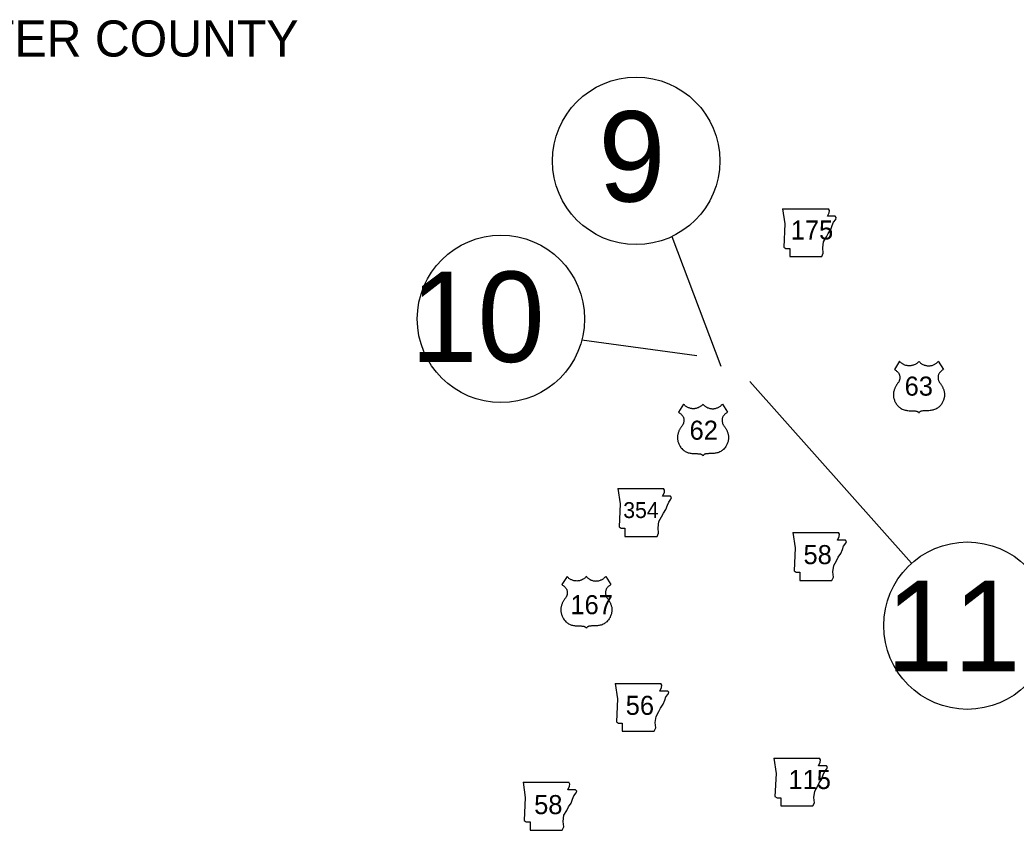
# Model space of a CAD drawing. Extents: x -819161 to 80911, y -6604 to 768454.
# Drawn here: x 45921 to 48407, y 4696 to 6716 of the extents above; entities that cross this region are included whole.
import ezdxf

# ---------------------------------------------------------------- set-up
doc = ezdxf.new("R2010")
doc.units = 0
for name, color, linetype in [('Default', 7, 'Continuous'), ('Level 21', 7, 'Continuous'), ('Level 22', 7, 'Continuous')]:
    doc.layers.add(name, color=color, linetype=linetype)

msp = doc.modelspace()

# ---------------------------------------------------------------- linework, layer by layer
at = {"layer": 'Default'}
for points in [[(47548.1, 6175.7), (47670.5, 5852.4)], [(47323.6, 5917.9), (47610.3, 5879.4)], [(47742.7, 5814.3), (48146.4, 5361.1)]]:
    msp.add_lwpolyline(points, dxfattribs=at)
for centre in [(47458.9, 6364.4), (47121.5, 5970.4), (48285.3, 5205.4)]:
    msp.add_circle(centre, 208.7, dxfattribs=at)
at = {"layer": 'Level 21'}
for p, q in [((47824.5, 6245.2), (47830.2, 6207.2)), ((47941.2, 6240.8), (47938.6, 6245.2)), ((47940.6, 6235.1), (47941.2, 6240.8)), ((47936.2, 6226.2), (47940.6, 6235.1)), ((47955.8, 6226.2), (47936.2, 6226.2)), ((47951.4, 6211.6), (47957.1, 6218.6)), ((47958.4, 6223), (47955.8, 6226.2)), ((47957.1, 6218.6), (47958.4, 6223)), ((47830.2, 6207.2), (47827.7, 6149.4)), ((47938.1, 6183.7), (47944.4, 6193.2)), ((47944.4, 6193.2), (47948.2, 6203.4)), ((47948.2, 6203.4), (47951.4, 6211.6)), ((47926.6, 6162.7), (47933.6, 6174.8)), ((47933.6, 6174.8), (47938.1, 6183.7)), ((47827.7, 6149.4), (47832.8, 6146.3)), ((47832.8, 6146.3), (47842.3, 6146.3)), ((47842.3, 6146.3), (47842.3, 6126)), ((47924.7, 6147.5), (47926.6, 6162.7)), ((47926, 6134.2), (47924.7, 6147.5)), ((47842.3, 6126), (47922.2, 6126)), ((47922.2, 6126), (47926, 6134.2)), ((47413.3, 5547.4), (47419, 5509.3)), ((47530.1, 5542.9), (47527.4, 5547.3)), ((47525, 5528.3), (47529.4, 5537.2)), ((47544.7, 5528.3), (47525, 5528.3)), ((47529.4, 5537.2), (47530.1, 5542.9)), ((47540.2, 5513.7), (47545.9, 5520.7)), ((47547.2, 5525.2), (47544.7, 5528.3)), ((47545.9, 5520.7), (47547.2, 5525.2)), ((47419, 5509.3), (47416.5, 5451.6)), ((47526.9, 5485.8), (47533.2, 5495.3)), ((47533.2, 5495.3), (47537.1, 5505.5)), ((47537.1, 5505.5), (47540.2, 5513.7)), ((47515.5, 5464.9), (47522.5, 5476.9)), ((47522.5, 5476.9), (47526.9, 5485.8)), ((47416.5, 5451.6), (47421.6, 5448.4)), ((47421.6, 5448.4), (47431.1, 5448.4)), ((47431.1, 5448.4), (47431.1, 5428.1)), ((47513.6, 5449.7), (47515.5, 5464.9)), ((47514.8, 5436.3), (47513.6, 5449.7)), ((47431.1, 5428.1), (47511, 5428.1)), ((47511, 5428.1), (47514.8, 5436.3)), ((47849.8, 5437.6), (47855.6, 5399.5)), ((47961.5, 5418.6), (47965.9, 5427.5)), ((47966.6, 5433.2), (47963.9, 5437.6)), ((47965.9, 5427.5), (47966.6, 5433.2)), ((47855.6, 5399.5), (47853, 5341.8)), ((47981.2, 5418.6), (47961.5, 5418.6)), ((47969.8, 5385.6), (47973.6, 5395.7)), ((47973.6, 5395.7), (47976.7, 5404)), ((47976.7, 5404), (47982.4, 5411)), ((47983.7, 5415.4), (47981.2, 5418.6)), ((47982.4, 5411), (47983.7, 5415.4)), ((47959, 5367.2), (47963.4, 5376.1)), ((47963.4, 5376.1), (47969.8, 5385.6)), ((47950.1, 5339.9), (47952, 5355.1)), ((47952, 5355.1), (47959, 5367.2)), ((47853, 5341.8), (47858.1, 5338.6)), ((47858.1, 5338.6), (47867.6, 5338.6)), ((47867.6, 5338.6), (47867.6, 5318.3)), ((47947.5, 5318.3), (47951.4, 5326.6)), ((47951.4, 5326.6), (47950.1, 5339.9)), ((47867.6, 5318.3), (47947.5, 5318.3)), ((47406.5, 5061.4), (47412.2, 5023.3)), ((47518.1, 5042.4), (47522.6, 5051.3)), ((47523.2, 5057), (47520.6, 5061.4)), ((47522.6, 5051.3), (47523.2, 5057)), ((47412.2, 5023.3), (47409.6, 4965.6)), ((47537.8, 5042.4), (47518.1, 5042.4)), ((47530.2, 5019.5), (47533.4, 5027.8)), ((47533.4, 5027.8), (47539.1, 5034.8)), ((47540.3, 5039.2), (47537.8, 5042.4)), ((47539.1, 5034.8), (47540.3, 5039.2)), ((47515.6, 4991), (47520, 4999.9)), ((47520, 4999.9), (47526.4, 5009.4)), ((47526.4, 5009.4), (47530.2, 5019.5)), ((47506.7, 4963.7), (47508.6, 4978.9)), ((47508.6, 4978.9), (47515.6, 4991)), ((47409.6, 4965.6), (47414.7, 4962.4)), ((47414.7, 4962.4), (47424.2, 4962.4)), ((47424.2, 4962.4), (47424.2, 4942.1)), ((47504.2, 4942.1), (47508, 4950.4)), ((47508, 4950.4), (47506.7, 4963.7)), ((47424.2, 4942.1), (47504.2, 4942.1)), ((47802.3, 4874.9), (47808, 4836.9)), ((47919, 4870.5), (47916.4, 4874.9)), ((47913.9, 4855.9), (47918.4, 4864.8)), ((47933.6, 4855.9), (47913.9, 4855.9)), ((47918.4, 4864.8), (47919, 4870.5)), ((47929.1, 4841.3), (47934.8, 4848.3)), ((47936.1, 4852.7), (47933.6, 4855.9)), ((47934.8, 4848.3), (47936.1, 4852.7)), ((47808, 4836.9), (47805.4, 4779.1)), ((47915.8, 4813.4), (47922.2, 4822.9)), ((47922.2, 4822.9), (47926, 4833.1)), ((47926, 4833.1), (47929.1, 4841.3)), ((47176.7, 4815), (47182.4, 4776.9)), ((47288.4, 4795.9), (47292.8, 4804.8)), ((47293.4, 4810.5), (47290.8, 4814.9)), ((47292.8, 4804.8), (47293.4, 4810.5)), ((47904.4, 4792.5), (47911.4, 4804.5)), ((47911.4, 4804.5), (47915.8, 4813.4)), ((47182.4, 4776.9), (47179.9, 4719.2)), ((47308, 4795.9), (47288.4, 4795.9)), ((47296.6, 4762.9), (47300.4, 4773.1)), ((47300.4, 4773.1), (47303.6, 4781.3)), ((47303.6, 4781.3), (47309.3, 4788.3)), ((47310.6, 4792.8), (47308, 4795.9)), ((47309.3, 4788.3), (47310.6, 4792.8)), ((47805.4, 4779.1), (47810.5, 4776)), ((47810.5, 4776), (47820, 4776)), ((47820, 4776), (47820, 4755.7)), ((47902.5, 4777.2), (47904.4, 4792.5)), ((47903.8, 4763.9), (47902.5, 4777.2)), ((47285.8, 4744.5), (47290.3, 4753.4)), ((47290.3, 4753.4), (47296.6, 4762.9)), ((47820, 4755.7), (47900, 4755.7)), ((47900, 4755.7), (47903.8, 4763.9)), ((47276.9, 4717.3), (47278.8, 4732.5)), ((47278.8, 4732.5), (47285.8, 4744.5)), ((47179.9, 4719.2), (47184.9, 4716)), ((47184.9, 4716), (47194.5, 4716)), ((47194.5, 4716), (47194.5, 4695.7)), ((47274.4, 4695.7), (47278.2, 4703.9)), ((47278.2, 4703.9), (47276.9, 4717.3)), ((47194.5, 4695.7), (47274.4, 4695.7))]:
    msp.add_line(p, q, dxfattribs=at)
for points in [[(47824.5, 6245.2), (47938.6, 6245.2)], [(47413.3, 5547.4), (47527.4, 5547.3)], [(47849.8, 5437.6), (47963.9, 5437.6)], [(47406.5, 5061.4), (47520.6, 5061.4)], [(47802.3, 4874.9), (47916.4, 4874.9)], [(47176.7, 4815), (47290.8, 4814.9)]]:
    msp.add_lwpolyline(points, dxfattribs=at)
at = {"layer": 'Level 22'}
for points in [[(48164.6, 5864.4), (48163.6, 5863.3), (48162.6, 5862.4), (48161.6, 5861.4), (48160.4, 5860.4), (48159.3, 5859.5), (48157.9, 5858.6), (48156.5, 5857.6), (48154.8, 5856.7), (48152.7, 5855.8), (48151.1, 5855.1), (48149.3, 5854.6), (48147.6, 5854.1), (48146.1, 5853.8), (48144.5, 5853.6), (48143, 5853.4), (48140.9, 5853.3), (48139.3, 5853.3), (48137.8, 5853.4), (48136.5, 5853.6), (48135.1, 5853.8), (48133.3, 5854.1), (48131.7, 5854.5), (48129.7, 5855.2), (48128.1, 5855.8), (48126.5, 5856.5), (48125.2, 5857.3), (48123.9, 5858), (48122.4, 5859), (48121.1, 5859.9), (48120, 5860.9), (48119, 5861.7), (48118.1, 5862.7), (48117.1, 5863.7), (48116.3, 5864.6), (48103.3, 5844.5), (48104.3, 5843.9), (48105.4, 5843.2), (48106.4, 5842.5), (48107.8, 5841.4), (48108.9, 5840.4), (48109.9, 5839.5), (48110.9, 5838.5), (48111.9, 5837.3), (48112.7, 5836.4), (48113.4, 5835.5), (48114.2, 5834.5), (48114.9, 5833.4), (48115.5, 5832.1), (48116, 5830.5), (48116.4, 5829), (48116.7, 5827.3), (48116.9, 5825.8), (48116.9, 5824.3), (48116.9, 5822.9), (48116.8, 5821.8), (48116.6, 5820.4), (48116.3, 5819.1), (48116, 5817.7), (48115.6, 5816.5), (48115.1, 5815.2), (48114.2, 5813.4), (48113.4, 5812), (48112.3, 5810.7), (48111, 5809.1), (48110, 5807.7), (48109, 5806.3), (48108.2, 5804.8), (48107.4, 5803.6), (48106.8, 5802.4), (48106, 5801), (48105.3, 5799.4), (48104.5, 5797.8), (48104.1, 5796.6), (48103.5, 5795.1), (48102.9, 5793.2), (48102.4, 5791.6), (48101.9, 5789.9), (48101.4, 5788), (48101.2, 5786.2), (48100.9, 5784.4), (48100.8, 5782.4), (48100.8, 5780.5), (48100.9, 5778.7), (48101.1, 5776.5), (48101.5, 5774.5), (48101.8, 5772.9), (48102.1, 5771.6), (48102.6, 5770), (48103.2, 5768.1), (48104, 5765.8), (48104.8, 5764.1), (48105.6, 5762.4), (48106.6, 5760.7), (48107.8, 5758.7), (48109.1, 5756.9), (48110.3, 5755.3), (48111.7, 5753.7), (48113.5, 5751.8), (48115, 5750.4), (48116.6, 5749.1)], [(48164.6, 5864.4), (48165.6, 5863.3), (48166.5, 5862.4), (48167.6, 5861.4), (48168.7, 5860.4), (48169.9, 5859.5), (48171.2, 5858.6), (48172.7, 5857.6), (48174.3, 5856.7), (48176.4, 5855.8), (48178, 5855.1), (48179.9, 5854.6), (48181.5, 5854.1), (48183.1, 5853.8), (48184.7, 5853.6), (48186.2, 5853.4), (48188.2, 5853.3), (48189.9, 5853.3), (48191.3, 5853.4), (48192.7, 5853.6), (48194.1, 5853.8), (48195.8, 5854.1), (48197.4, 5854.5), (48199.4, 5855.2), (48201.1, 5855.8), (48202.6, 5856.5), (48204, 5857.3), (48205.3, 5858), (48206.7, 5859), (48208, 5859.9), (48209.2, 5860.9), (48210.1, 5861.7), (48211.1, 5862.7), (48212.1, 5863.7), (48212.8, 5864.6), (48225.8, 5844.5), (48224.9, 5843.9), (48223.8, 5843.2), (48222.7, 5842.5), (48221.3, 5841.4), (48220.2, 5840.4), (48219.2, 5839.5), (48218.2, 5838.5), (48217.2, 5837.3), (48216.5, 5836.4), (48215.7, 5835.5), (48215, 5834.5), (48214.3, 5833.4), (48213.6, 5832.1), (48213.1, 5830.5), (48212.7, 5829), (48212.4, 5827.3), (48212.3, 5825.8), (48212.2, 5824.3), (48212.3, 5822.9), (48212.4, 5821.8), (48212.6, 5820.4), (48212.8, 5819.1), (48213.2, 5817.7), (48213.6, 5816.5), (48214.1, 5815.2), (48214.9, 5813.4), (48215.8, 5812), (48216.8, 5810.7), (48218.1, 5809.1), (48219.1, 5807.7), (48220.1, 5806.3), (48221, 5804.8), (48221.7, 5803.6), (48222.4, 5802.4), (48223.1, 5801), (48223.9, 5799.4), (48224.6, 5797.8), (48225.1, 5796.6), (48225.7, 5795.1), (48226.3, 5793.2), (48226.8, 5791.6), (48227.3, 5789.9), (48227.7, 5788), (48228, 5786.2), (48228.2, 5784.4), (48228.3, 5782.4), (48228.3, 5780.5), (48228.3, 5778.7), (48228, 5776.5), (48227.7, 5774.5), (48227.4, 5772.9), (48227, 5771.6), (48226.6, 5770), (48226, 5768.1), (48225.1, 5765.8), (48224.4, 5764.1), (48223.5, 5762.4), (48222.6, 5760.7), (48221.3, 5758.7), (48220.1, 5756.9), (48218.9, 5755.3), (48217.5, 5753.7), (48215.7, 5751.8), (48214.2, 5750.4), (48212.6, 5749.1)], [(47625.8, 5757.6), (47624.8, 5756.5), (47623.8, 5755.5), (47622.8, 5754.5), (47621.6, 5753.5), (47620.5, 5752.6), (47619.1, 5751.7), (47617.7, 5750.8), (47616, 5749.9), (47613.9, 5748.9), (47612.3, 5748.3), (47610.5, 5747.7), (47608.8, 5747.2), (47607.3, 5746.9), (47605.7, 5746.7), (47604.2, 5746.5), (47602.1, 5746.4), (47600.5, 5746.5), (47599, 5746.5), (47597.7, 5746.7), (47596.3, 5746.9), (47594.5, 5747.3), (47592.9, 5747.7), (47590.9, 5748.3), (47589.3, 5749), (47587.7, 5749.7), (47586.3, 5750.4), (47585.1, 5751.2), (47583.6, 5752.1), (47582.3, 5753.1), (47581.2, 5754), (47580.2, 5754.8), (47579.2, 5755.8), (47578.3, 5756.8), (47577.5, 5757.7), (47564.5, 5737.6), (47565.5, 5737.1), (47566.6, 5736.3), (47567.6, 5735.6), (47569, 5734.5), (47570.1, 5733.5), (47571.1, 5732.6), (47572.1, 5731.6), (47573.1, 5730.5), (47573.9, 5729.6), (47574.6, 5728.6), (47575.3, 5727.6), (47576.1, 5726.5), (47576.7, 5725.2), (47577.2, 5723.7), (47577.6, 5722.1), (47577.9, 5720.5), (47578.1, 5718.9), (47578.1, 5717.4), (47578.1, 5716), (47578, 5714.9), (47577.8, 5713.6), (47577.5, 5712.3), (47577.2, 5710.9), (47576.8, 5709.7), (47576.3, 5708.3), (47575.4, 5706.5), (47574.5, 5705.1), (47573.5, 5703.9), (47572.2, 5702.2), (47571.2, 5700.8), (47570.2, 5699.4), (47569.4, 5698), (47568.6, 5696.7), (47568, 5695.5), (47567.2, 5694.1), (47566.4, 5692.5), (47565.7, 5690.9), (47565.2, 5689.7), (47564.7, 5688.2), (47564, 5686.3), (47563.5, 5684.8), (47563.1, 5683.1), (47562.6, 5681.1), (47562.3, 5679.3), (47562.1, 5677.5), (47562, 5675.5), (47562, 5673.6), (47562.1, 5671.8), (47562.3, 5669.6), (47562.6, 5667.6), (47563, 5666.1), (47563.3, 5664.7), (47563.8, 5663.2), (47564.4, 5661.3), (47565.2, 5659), (47566, 5657.3), (47566.8, 5655.5), (47567.8, 5653.8), (47569, 5651.8), (47570.3, 5650), (47571.5, 5648.4), (47572.9, 5646.8), (47574.7, 5644.9), (47576.2, 5643.5), (47577.8, 5642.2)], [(47625.8, 5757.6), (47626.8, 5756.5), (47627.7, 5755.5), (47628.8, 5754.5), (47629.9, 5753.5), (47631, 5752.6), (47632.4, 5751.7), (47633.9, 5750.8), (47635.5, 5749.9), (47637.6, 5748.9), (47639.2, 5748.3), (47641, 5747.7), (47642.7, 5747.2), (47644.2, 5746.9), (47645.9, 5746.7), (47647.4, 5746.5), (47649.4, 5746.4), (47651.1, 5746.5), (47652.5, 5746.5), (47653.9, 5746.7), (47655.3, 5746.9), (47657, 5747.3), (47658.6, 5747.7), (47660.6, 5748.3), (47662.3, 5749), (47663.8, 5749.7), (47665.2, 5750.4), (47666.5, 5751.2), (47667.9, 5752.1), (47669.2, 5753.1), (47670.4, 5754), (47671.3, 5754.8), (47672.3, 5755.8), (47673.2, 5756.8), (47674, 5757.7), (47687, 5737.6), (47686.1, 5737.1), (47685, 5736.3), (47683.9, 5735.6), (47682.5, 5734.5), (47681.4, 5733.5), (47680.4, 5732.6), (47679.4, 5731.6), (47678.4, 5730.5), (47677.7, 5729.6), (47676.9, 5728.6), (47676.2, 5727.6), (47675.5, 5726.5), (47674.8, 5725.2), (47674.3, 5723.7), (47673.9, 5722.1), (47673.6, 5720.5), (47673.5, 5718.9), (47673.4, 5717.4), (47673.5, 5716), (47673.6, 5714.9), (47673.7, 5713.6), (47674, 5712.3), (47674.4, 5710.9), (47674.7, 5709.7), (47675.3, 5708.3), (47676.1, 5706.5), (47677, 5705.1), (47678, 5703.9), (47679.3, 5702.2), (47680.3, 5700.8), (47681.3, 5699.4), (47682.2, 5698), (47682.9, 5696.7), (47683.6, 5695.5), (47684.3, 5694.1), (47685.1, 5692.5), (47685.8, 5690.9), (47686.3, 5689.7), (47686.9, 5688.2), (47687.5, 5686.3), (47688, 5684.8), (47688.5, 5683.1), (47688.9, 5681.1), (47689.2, 5679.3), (47689.4, 5677.5), (47689.5, 5675.5), (47689.5, 5673.6), (47689.4, 5671.8), (47689.2, 5669.6), (47688.9, 5667.6), (47688.5, 5666.1), (47688.2, 5664.7), (47687.7, 5663.2), (47687.2, 5661.3), (47686.3, 5659), (47685.6, 5657.3), (47684.7, 5655.5), (47683.8, 5653.8), (47682.5, 5651.8), (47681.3, 5650), (47680.1, 5648.4), (47678.7, 5646.8), (47676.9, 5644.9), (47675.3, 5643.5), (47673.8, 5642.2)], [(48116.6, 5749.1), (48118.2, 5747.9), (48120.2, 5746.6), (48122.6, 5745.5), (48125.5, 5744.4), (48127.8, 5743.6), (48129.9, 5743), (48132.3, 5742.5), (48134.6, 5742.1), (48137, 5741.7), (48140, 5741.5), (48142.3, 5741.4), (48144.3, 5741.4), (48146.3, 5741.4), (48148.2, 5741.3), (48150, 5741.2), (48151.6, 5741.1), (48153.2, 5741), (48155.2, 5740.8), (48157.2, 5740.5), (48158.4, 5740.4), (48159.3, 5740.2), (48160.5, 5739.7), (48161.2, 5739.3), (48161.8, 5738.9), (48162.6, 5738.3), (48163.4, 5737.5), (48164, 5736.7), (48164.6, 5735.7)], [(48212.6, 5749.1), (48211, 5747.9), (48209, 5746.6), (48206.5, 5745.5), (48203.7, 5744.4), (48201.3, 5743.6), (48199.2, 5743), (48196.8, 5742.5), (48194.6, 5742.1), (48192.2, 5741.7), (48189.1, 5741.5), (48186.8, 5741.4), (48184.8, 5741.4), (48182.9, 5741.4), (48181, 5741.3), (48179.1, 5741.2), (48177.5, 5741.1), (48176, 5741), (48173.9, 5740.8), (48172, 5740.5), (48170.8, 5740.4), (48169.8, 5740.2), (48168.6, 5739.7), (48168, 5739.3), (48167.4, 5738.9), (48166.6, 5738.3), (48165.8, 5737.5), (48165.1, 5736.7), (48164.6, 5735.7)], [(47577.8, 5642.2), (47579.4, 5641), (47581.3, 5639.7), (47583.8, 5638.6), (47586.7, 5637.5), (47589, 5636.7), (47591.1, 5636.2), (47593.5, 5635.6), (47595.8, 5635.2), (47598.2, 5634.9), (47601.2, 5634.6), (47603.5, 5634.5), (47605.5, 5634.5), (47607.4, 5634.5), (47609.4, 5634.5), (47611.2, 5634.4), (47612.8, 5634.3), (47614.4, 5634.1), (47616.4, 5633.9), (47618.4, 5633.7), (47619.6, 5633.5), (47620.5, 5633.3), (47621.7, 5632.8), (47622.4, 5632.4), (47623, 5632.1), (47623.8, 5631.4), (47624.6, 5630.6), (47625.2, 5629.8), (47625.8, 5628.9)], [(47673.8, 5642.2), (47672.1, 5641), (47670.2, 5639.7), (47667.7, 5638.6), (47664.9, 5637.5), (47662.5, 5636.7), (47660.4, 5636.2), (47658, 5635.6), (47655.8, 5635.2), (47653.4, 5634.9), (47650.3, 5634.6), (47648, 5634.5), (47646, 5634.5), (47644.1, 5634.5), (47642.2, 5634.5), (47640.3, 5634.4), (47638.7, 5634.3), (47637.1, 5634.1), (47635.1, 5633.9), (47633.2, 5633.7), (47632, 5633.5), (47631, 5633.3), (47629.8, 5632.8), (47629.1, 5632.4), (47628.6, 5632.1), (47627.7, 5631.4), (47627, 5630.6), (47626.3, 5629.8), (47625.8, 5628.9)], [(47334.7, 5327.9), (47333.7, 5326.8), (47332.8, 5325.8), (47331.7, 5324.8), (47330.6, 5323.8), (47329.4, 5322.9), (47328.1, 5322), (47326.6, 5321.1), (47325, 5320.2), (47322.9, 5319.2), (47321.3, 5318.6), (47319.4, 5318), (47317.8, 5317.5), (47316.2, 5317.2), (47314.6, 5317), (47313.1, 5316.8), (47311.1, 5316.7), (47309.4, 5316.8), (47308, 5316.8), (47306.6, 5317), (47305.2, 5317.2), (47303.5, 5317.6), (47301.9, 5318), (47299.9, 5318.6), (47298.2, 5319.3), (47296.7, 5320), (47295.3, 5320.7), (47294, 5321.5), (47292.6, 5322.4), (47291.3, 5323.4), (47290.1, 5324.3), (47289.2, 5325.1), (47288.2, 5326.1), (47287.2, 5327.1), (47286.5, 5328), (47273.5, 5307.9), (47274.4, 5307.4), (47275.5, 5306.6), (47276.6, 5305.9), (47278, 5304.8), (47279.1, 5303.8), (47280.1, 5302.9), (47281.1, 5301.9), (47282.1, 5300.8), (47282.8, 5299.9), (47283.6, 5298.9), (47284.3, 5297.9), (47285, 5296.8), (47285.7, 5295.5), (47286.2, 5294), (47286.6, 5292.4), (47286.9, 5290.8), (47287, 5289.2), (47287.1, 5287.7), (47287, 5286.3), (47286.9, 5285.2), (47286.7, 5283.9), (47286.5, 5282.6), (47286.1, 5281.2), (47285.7, 5280), (47285.2, 5278.6), (47284.4, 5276.8), (47283.5, 5275.4), (47282.5, 5274.2), (47281.2, 5272.5), (47280.2, 5271.1), (47279.2, 5269.7), (47278.3, 5268.3), (47277.6, 5267), (47276.9, 5265.8), (47276.2, 5264.4), (47275.4, 5262.8), (47274.7, 5261.2), (47274.2, 5260), (47273.6, 5258.5), (47273, 5256.6), (47272.5, 5255.1), (47272, 5253.4), (47271.6, 5251.4), (47271.3, 5249.6), (47271.1, 5247.8), (47271, 5245.8), (47271, 5243.9), (47271, 5242.1), (47271.3, 5239.9), (47271.6, 5237.9), (47271.9, 5236.4), (47272.3, 5235), (47272.7, 5233.5), (47273.3, 5231.6), (47274.2, 5229.3), (47274.9, 5227.6), (47275.8, 5225.8), (47276.7, 5224.1), (47278, 5222.1), (47279.2, 5220.3), (47280.4, 5218.7), (47281.8, 5217.1), (47283.6, 5215.2), (47285.1, 5213.8), (47286.7, 5212.5)], [(47334.7, 5327.9), (47335.7, 5326.8), (47336.7, 5325.8), (47337.7, 5324.8), (47338.9, 5323.8), (47340, 5322.9), (47341.4, 5322), (47342.8, 5321.1), (47344.5, 5320.2), (47346.6, 5319.2), (47348.2, 5318.6), (47350, 5318), (47351.7, 5317.5), (47353.2, 5317.2), (47354.8, 5317), (47356.3, 5316.8), (47358.4, 5316.7), (47360, 5316.8), (47361.5, 5316.8), (47362.8, 5317), (47364.2, 5317.2), (47366, 5317.6), (47367.6, 5318), (47369.6, 5318.6), (47371.2, 5319.3), (47372.8, 5320), (47374.1, 5320.7), (47375.4, 5321.5), (47376.9, 5322.4), (47378.2, 5323.4), (47379.3, 5324.3), (47380.3, 5325.1), (47381.2, 5326.1), (47382.2, 5327.1), (47383, 5328), (47396, 5307.9), (47395, 5307.4), (47393.9, 5306.6), (47392.9, 5305.9), (47391.5, 5304.8), (47390.4, 5303.8), (47389.4, 5302.9), (47388.4, 5301.9), (47387.4, 5300.8), (47386.6, 5299.9), (47385.9, 5298.9), (47385.1, 5297.9), (47384.4, 5296.8), (47383.8, 5295.5), (47383.3, 5294), (47382.9, 5292.4), (47382.6, 5290.8), (47382.4, 5289.2), (47382.4, 5287.7), (47382.4, 5286.3), (47382.5, 5285.2), (47382.7, 5283.9), (47383, 5282.6), (47383.3, 5281.2), (47383.7, 5280), (47384.2, 5278.6), (47385.1, 5276.8), (47385.9, 5275.4), (47387, 5274.2), (47388.3, 5272.5), (47389.3, 5271.1), (47390.3, 5269.7), (47391.1, 5268.3), (47391.9, 5267), (47392.5, 5265.8), (47393.3, 5264.4), (47394, 5262.8), (47394.8, 5261.2), (47395.2, 5260), (47395.8, 5258.5), (47396.4, 5256.6), (47396.9, 5255.1), (47397.4, 5253.4), (47397.9, 5251.4), (47398.1, 5249.6), (47398.4, 5247.8), (47398.5, 5245.8), (47398.5, 5243.9), (47398.4, 5242.1), (47398.2, 5239.9), (47397.8, 5237.9), (47397.5, 5236.4), (47397.2, 5235), (47396.7, 5233.5), (47396.1, 5231.6), (47395.3, 5229.3), (47394.5, 5227.6), (47393.7, 5225.8), (47392.7, 5224.1), (47391.5, 5222.1), (47390.2, 5220.3), (47389, 5218.7), (47387.6, 5217.1), (47385.8, 5215.2), (47384.3, 5213.8), (47382.7, 5212.5)], [(47286.7, 5212.5), (47288.3, 5211.3), (47290.3, 5210), (47292.8, 5208.9), (47295.6, 5207.8), (47298, 5207), (47300.1, 5206.5), (47302.5, 5205.9), (47304.7, 5205.5), (47307.1, 5205.2), (47310.2, 5204.9), (47312.5, 5204.8), (47314.5, 5204.8), (47316.4, 5204.8), (47318.3, 5204.8), (47320.2, 5204.7), (47321.8, 5204.6), (47323.3, 5204.4), (47325.4, 5204.2), (47327.3, 5204), (47328.5, 5203.8), (47329.5, 5203.6), (47330.7, 5203.1), (47331.3, 5202.7), (47331.9, 5202.4), (47332.7, 5201.7), (47333.5, 5200.9), (47334.2, 5200.1), (47334.7, 5199.2)], [(47382.7, 5212.5), (47381.1, 5211.3), (47379.1, 5210), (47376.7, 5208.9), (47373.8, 5207.8), (47371.5, 5207), (47369.4, 5206.5), (47367, 5205.9), (47364.7, 5205.5), (47362.3, 5205.2), (47359.3, 5204.9), (47357, 5204.8), (47355, 5204.8), (47353, 5204.8), (47351.1, 5204.8), (47349.3, 5204.7), (47347.7, 5204.6), (47346.1, 5204.4), (47344.1, 5204.2), (47342.1, 5204), (47340.9, 5203.8), (47340, 5203.6), (47338.8, 5203.1), (47338.1, 5202.7), (47337.5, 5202.4), (47336.7, 5201.7), (47335.9, 5200.9), (47335.3, 5200.1), (47334.7, 5199.2)]]:
    msp.add_lwpolyline(points, dxfattribs=at)

# ---------------------------------------------------------------- texts
at = {"layer": 'Default'}
for s, height, p in [('BAXTER COUNTY', 90, (45593.3, 6624.6)), ('9', 225.4, (47364.7, 6262.9)), ('10', 225.42, (46895.4, 5863)), ('11', 225.42, (48082.7, 5091.9))]:
    msp.add_text(s, height=height, dxfattribs=at).set_placement(p)
at = {"layer": 'Level 21'}
for s, height, p in [('175', 47.52, (47844.7, 6168.3)), ('354', 39.6, (47426.8, 5473.8)), ('58', 47.52, (47876.5, 5358.8)), ('56', 47.52, (47432.9, 4983)), ('115', 47.52, (47838.9, 4798)), ('58', 47.52, (47204.4, 4735.4))]:
    msp.add_text(s, height=height, dxfattribs=at).set_placement(p)
at = {"layer": 'Level 22'}
for s, p in [('63', (48128.9, 5779)), ('62', (47592.2, 5669.1)), ('167', (47294.9, 5234))]:
    msp.add_text(s, height=47.52, dxfattribs=at).set_placement(p)

doc.saveas('drawing.dxf')
